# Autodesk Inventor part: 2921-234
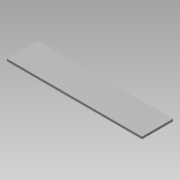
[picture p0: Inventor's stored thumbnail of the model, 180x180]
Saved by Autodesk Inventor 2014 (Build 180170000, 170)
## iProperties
Company: NHTSA/VRTC
Created: 2012-08
Part Number: 2921-234
Material: Steel, Mild
Document SubType Name: Modeling
Designer: Mike Vanvoorhis
Density: 7.86 g/cm^3
Mass: 1718.71 g
Surface Area: 749.192 cm^2
Volume: 218.665 cm^3
Description: HONEYCOMB FRAME HONEYCOMB SUPPORT PLATE
Project: CHILD SIDE IMPACT SLED
Stock Number: PL 6.4 (1/4") x 88.9 (3 1/2") x 387.4 (15 1/4")
Appearance: Steel
Author: Dave Walker
Title: Honeycomb Frame Hexcel Support Plate
Subject: Child Side Impact Sled
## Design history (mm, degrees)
sketch "Sketch1"
  geometry: L1 (0, 0)-(387.35, 0); L2 (387.35, 0)-(387.35, 6.35); L3 (387.35, 6.35)-(0, 6.35); L4 (0, 6.35)-(0, 0)
  constraints: 8 end point, 2 parallel, 1 horizontal, 1 perpendicular
  dimensions: "d0" = 387.35 distance of L3.end L2.end; "d1" = 6.35 distance of L2.end L1.end
extrude "Extrusion1" new body sketch "Sketch1" distance "d2" = 88.9; taper "d3" = 0 deg
body "Solid1"
